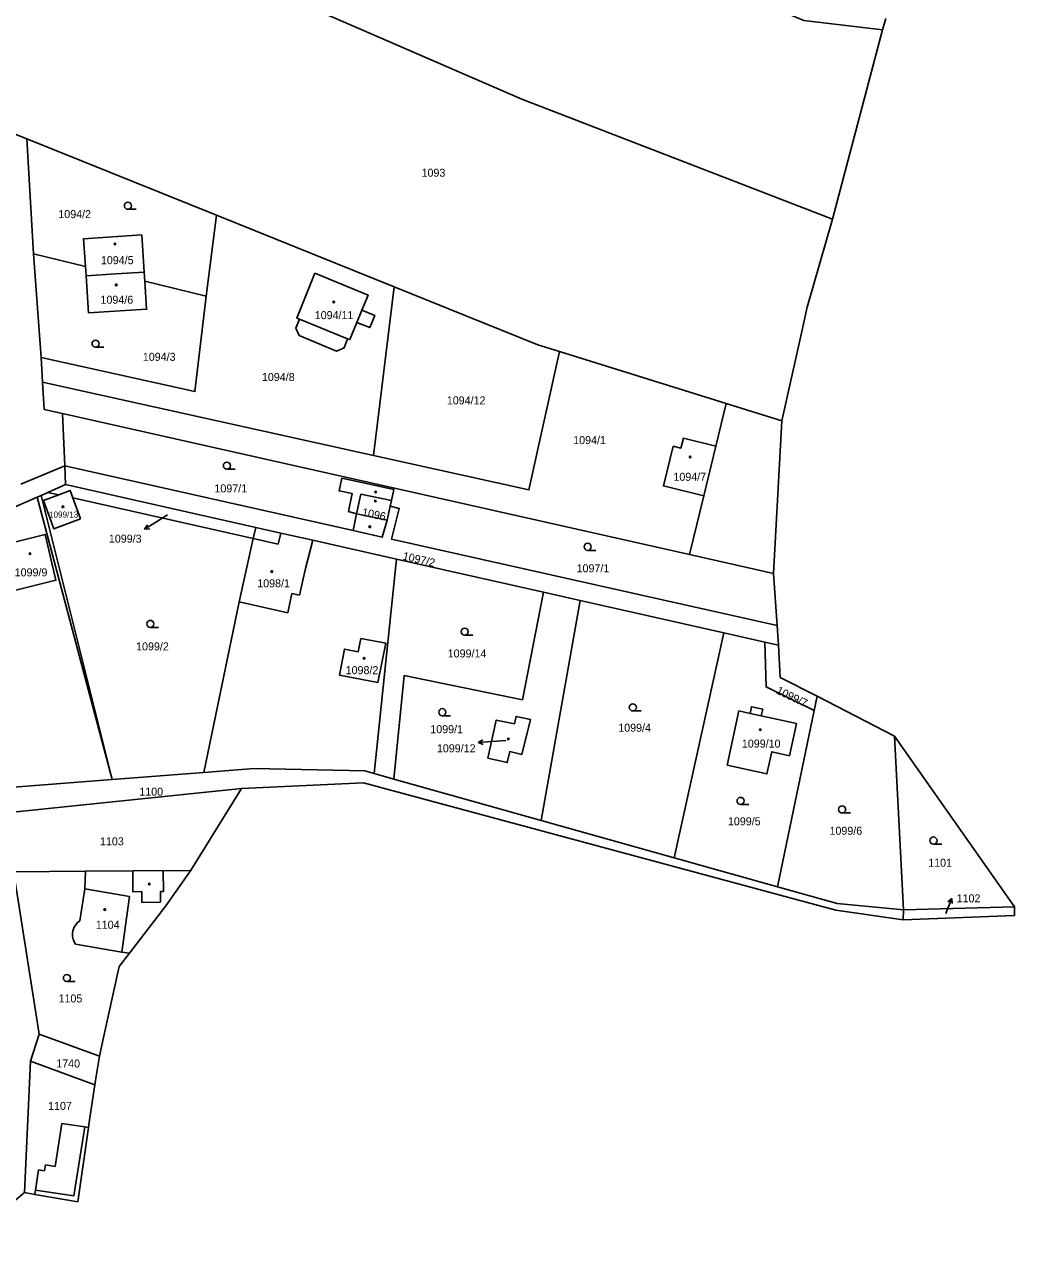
# Model space of a CAD drawing. Extents: x -724107 to -720612, y -1045267 to -1038441.
# Drawn here: x -721970.9 to -721760.5, y -1044478.1 to -1044219.7 of the extents above; entities that cross this region are included whole.
import ezdxf

# ---------------------------------------------------------------- set-up
doc = ezdxf.new("R2010")
doc.units = 0
for name, color, linetype in [('Hranice kat_území', 7, 'Continuous'), ('Hranice parcel', 7, 'Continuous'), ('Parcelní čísla', 7, 'Continuous'), ('Pop  PČ popisy', 7, 'Continuous'), ('Vnitřní kresba', 7, 'Continuous'), ('Značky budov', 7, 'Continuous'), ('Značky kultur', 7, 'Continuous')]:
    doc.layers.add(name, color=color, linetype=linetype)

msp = doc.modelspace()

# ---------------------------------------------------------------- linework, layer by layer
at = {"layer": 'Hranice kat_území'}
for p, q in [((-721788.61, -1044220.82), (-721787.91, -1044218.39)), ((-721799.2, -1044261.03), (-721788.61, -1044220.82)), ((-721809.96, -1044303.87), (-721805.88, -1044285.54)), ((-721811.72, -1044336.23), (-721809.96, -1044303.87)), ((-721810.96, -1044347.32), (-721811.72, -1044336.23)), ((-721810.68, -1044351.47), (-721810.96, -1044347.32)), ((-721786.01, -1044370.79), (-721802.48, -1044362.34)), ((-721760.55, -1044407.07), (-721786.01, -1044370.79)), ((-721935.62, -1044399.39), (-721924.74, -1044381.95)), ((-721940.82, -1044406.84), (-721935.62, -1044399.39)), ((-721948.56, -1044416.87), (-721940.82, -1044406.84)), ((-721798.52, -1044407.76), (-721784.21, -1044409.79)), ((-721784.21, -1044409.79), (-721760.51, -1044408.87)), ((-721760.55, -1044407.07), (-721760.51, -1044408.87)), ((-721954.95, -1044438.78), (-721954.21, -1044435.41)), ((-721955.57, -1044442.6), (-721954.95, -1044438.78)), ((-721955.93, -1044444.84), (-721955.57, -1044442.6))]:
    msp.add_line(p, q, dxfattribs=at)
for points in [[(-721805.88, -1044285.54), (-721804.58, -1044279.71), (-721799.2, -1044261.03)], [(-721802.48, -1044362.34), (-721810.3, -1044358.32), (-721810.68, -1044351.47)], [(-721924.74, -1044381.95), (-721898.87, -1044380.72), (-721798.52, -1044407.76)], [(-721954.21, -1044435.41), (-721950.76, -1044419.71), (-721948.56, -1044416.87)], [(-721957.14, -1044452.84), (-721956.99, -1044451.82), (-721955.93, -1044444.84)], [(-721959.54, -1044469.67), (-721957.29, -1044453.91), (-721957.14, -1044452.84)], [(-721970.87, -1044467.72), (-721972.74, -1044469.26), (-721979.36, -1044474.72), (-721983.52, -1044478.14)], [(-721959.54, -1044469.67), (-721968.69, -1044468.1), (-721970.87, -1044467.72)]]:
    msp.add_lwpolyline(points, dxfattribs=at)
at = {"layer": 'Hranice parcel'}
for p, q in [((-721975.92, -1044241.74), (-721970.35, -1044243.98)), ((-721970.35, -1044243.98), (-721930.09, -1044260.2)), ((-721970.35, -1044243.98), (-721968.98, -1044268.36)), ((-721932.24, -1044277.37), (-721930.09, -1044260.2)), ((-721930.09, -1044260.2), (-721892.33, -1044275.41)), ((-721968.98, -1044268.36), (-721957.91, -1044271.07)), ((-721968.98, -1044268.36), (-721967.36, -1044290.4)), ((-721957.78, -1044273.07), (-721957.91, -1044271.07)), ((-721945.46, -1044272.25), (-721945.34, -1044274.16)), ((-721945.34, -1044274.16), (-721932.24, -1044277.37)), ((-721896.72, -1044311.2), (-721892.33, -1044275.41)), ((-721857.19, -1044289.15), (-721821.77, -1044300.19)), ((-721967.03, -1044295.6), (-721967.36, -1044290.4)), ((-721896.72, -1044311.2), (-721967.03, -1044295.6)), ((-721821.77, -1044300.19), (-721809.96, -1044303.87)), ((-721962.77, -1044302.29), (-721829.61, -1044332.21)), ((-721962.32, -1044313.4), (-721962.77, -1044302.29)), ((-721971.64, -1044317.31), (-721962.32, -1044313.4)), ((-721962.32, -1044313.4), (-721901.08, -1044327.14)), ((-721962.32, -1044313.4), (-721962.16, -1044317.4)), ((-721965.9, -1044319.03), (-721962.16, -1044317.4)), ((-721962.16, -1044317.4), (-721921.75, -1044326.49)), ((-721967.33, -1044319.67), (-721965.9, -1044319.03)), ((-721952.21, -1044380), (-721967.33, -1044319.67)), ((-721966.83, -1044320.75), (-721963.56, -1044319.55)), ((-721963.56, -1044319.55), (-721965.9, -1044319.03)), ((-721960.58, -1044320.22), (-721958.97, -1044324.63)), ((-721922.27, -1044328.82), (-721960.58, -1044320.22)), ((-721922.27, -1044328.82), (-721921.75, -1044326.49)), ((-721896.57, -1044378.74), (-721891.86, -1044333.21)), ((-721891.86, -1044333.21), (-721860.58, -1044340.24)), ((-721829.61, -1044332.21), (-721811.72, -1044336.23)), ((-721860.58, -1044340.24), (-721852.85, -1044341.98)), ((-721861.08, -1044388.69), (-721852.85, -1044341.98)), ((-721852.85, -1044341.98), (-721822.32, -1044348.85)), ((-721832.85, -1044396.61), (-721822.32, -1044348.85)), ((-721822.32, -1044348.85), (-721813.61, -1044350.81)), ((-721813.61, -1044350.81), (-721810.68, -1044351.47)), ((-721802.48, -1044362.34), (-721803.11, -1044365.37)), ((-721810.87, -1044402.77), (-721803.11, -1044365.37)), ((-721784.16, -1044407.69), (-721786.01, -1044370.79)), ((-721978.83, -1044382.04), (-721952.21, -1044380)), ((-721932.77, -1044378.52), (-721952.21, -1044380)), ((-721892.41, -1044379.91), (-721896.57, -1044378.74)), ((-721892.41, -1044379.91), (-721861.08, -1044388.69)), ((-721977.33, -1044387.33), (-721924.74, -1044381.95)), ((-721861.08, -1044388.69), (-721832.85, -1044396.61)), ((-721832.85, -1044396.61), (-721810.87, -1044402.77)), ((-721973.2, -1044399.62), (-721957.88, -1044399.48)), ((-721784.21, -1044409.79), (-721784.16, -1044407.69)), ((-721784.16, -1044407.69), (-721760.55, -1044407.07)), ((-721967.74, -1044434.1), (-721969.56, -1044439.8)), ((-721967.74, -1044434.1), (-721954.95, -1044438.78)), ((-721969.56, -1044439.8), (-721970.87, -1044467.72)), ((-721955.93, -1044444.84), (-721969.56, -1044439.8))]:
    msp.add_line(p, q, dxfattribs=at)
for points in [[(-721961.47, -1044153.93), (-721895.13, -1044181.3), (-721805.29, -1044218.87), (-721788.61, -1044220.82)], [(-721968.11, -1044190.86), (-721865.19, -1044235.55), (-721799.2, -1044261.03)], [(-721957.91, -1044271.07), (-721958.3, -1044265.17), (-721945.97, -1044264.37), (-721945.46, -1044272.25)], [(-721957.78, -1044273.07), (-721951.48, -1044272.65), (-721945.46, -1044272.25)], [(-721945.34, -1044274.16), (-721944.95, -1044280.15), (-721957.26, -1044280.94), (-721957.78, -1044273.07)], [(-721899.21, -1044280.38), (-721896.46, -1044281.49), (-721897.5, -1044284.06), (-721900.26, -1044282.98), (-721901.73, -1044286.6), (-721902.25, -1044286.4), (-721902.96, -1044288.35), (-721904.56, -1044289.03), (-721912.53, -1044285.74), (-721913.26, -1044284.16), (-721912.45, -1044282.25), (-721912.99, -1044282.01), (-721909.16, -1044272.51), (-721897.89, -1044277.13), (-721899.21, -1044280.38)], [(-721892.33, -1044275.41), (-721861.83, -1044287.7), (-721857.19, -1044289.15)], [(-721967.36, -1044290.4), (-721934.68, -1044297.65), (-721932.24, -1044277.37)], [(-721857.19, -1044289.15), (-721863.7, -1044318.53), (-721896.72, -1044311.2)], [(-721967.03, -1044295.6), (-721966.66, -1044301.41), (-721962.77, -1044302.29)], [(-721829.61, -1044332.21), (-721826.56, -1044319.75), (-721835.14, -1044317.66), (-721833.06, -1044309.24), (-721831.4, -1044309.64), (-721830.89, -1044307.55), (-721823.99, -1044309.24), (-721821.77, -1044300.19)], [(-721893.21, -1044321.97), (-721892.91, -1044320.76), (-721892.38, -1044318.46), (-721903.45, -1044316.05), (-721904.03, -1044318.71), (-721901.24, -1044319.28), (-721902.03, -1044323.11), (-721900.31, -1044323.61), (-721901.08, -1044327.14)], [(-721967.33, -1044319.67), (-721968.19, -1044320.04), (-721998.33, -1044333.24)], [(-721958.97, -1044324.63), (-721964.66, -1044326.76), (-721966.83, -1044320.75)], [(-721963.56, -1044319.55), (-721961.15, -1044318.67), (-721960.58, -1044320.22)], [(-721901.08, -1044327.14), (-721894.86, -1044328.52), (-721893.85, -1044324.97), (-721893.21, -1044321.97)], [(-721893.21, -1044321.97), (-721891.27, -1044322.46), (-721892.91, -1044328.96), (-721810.96, -1044347.32)], [(-721972.97, -1044339.87), (-721976.27, -1044340.69), (-721978.48, -1044330.95), (-721975.23, -1044330.15), (-721966.5, -1044327.98), (-721964.21, -1044337.7), (-721972.97, -1044339.87)], [(-721932.77, -1044378.52), (-721925.29, -1044342.26), (-721922.27, -1044328.82)], [(-721921.75, -1044326.49), (-721916.44, -1044327.68), (-721909.6, -1044329.22), (-721891.86, -1044333.21)], [(-721860.58, -1044340.24), (-721865.09, -1044363.07), (-721890.21, -1044357.95), (-721892.41, -1044379.91)], [(-721895.79, -1044359.43), (-721903.92, -1044357.88), (-721902.9, -1044352.32), (-721899.95, -1044352.88), (-721899.41, -1044350.07), (-721894.13, -1044351.09), (-721895.79, -1044359.43)], [(-721803.11, -1044365.37), (-721813.32, -1044360.35), (-721813.61, -1044350.81)], [(-721821.61, -1044376.96), (-721819.1, -1044365.45), (-721816.73, -1044365.97), (-721816.42, -1044364.54), (-721814.03, -1044365.07), (-721814.35, -1044366.49), (-721806.87, -1044368.14), (-721808.38, -1044374.95), (-721812.11, -1044374.12), (-721813.15, -1044378.83), (-721821.61, -1044376.96)], [(-721872.42, -1044375.47), (-721870.64, -1044367.39), (-721866.8, -1044368.15), (-721866.42, -1044366.6), (-721863.39, -1044367.23), (-721865.21, -1044374.68), (-721867.77, -1044374.09), (-721868.3, -1044376.42), (-721872.42, -1044375.47)], [(-721896.57, -1044378.74), (-721898.55, -1044378.18), (-721922.09, -1044377.7), (-721932.77, -1044378.52)], [(-721973.2, -1044399.62), (-721972.16, -1044406.09), (-721967.74, -1044434.1)], [(-721957.88, -1044399.48), (-721958.04, -1044403.21), (-721959.14, -1044410.02)], [(-721957.88, -1044399.48), (-721947.83, -1044399.38), (-721941.4, -1044399.32), (-721935.62, -1044399.39)], [(-721810.87, -1044402.77), (-721798.21, -1044406.32), (-721784.16, -1044407.69)], [(-721959.14, -1044410.02), (-721959.6, -1044410.4), (-721959.99, -1044410.84), (-721960.31, -1044411.35), (-721960.53, -1044411.9), (-721960.6, -1044412.17), (-721960.68, -1044412.76), (-721960.66, -1044413.35), (-721960.55, -1044413.93), (-721960.33, -1044414.49), (-721960.03, -1044415)], [(-721960.03, -1044415), (-721950.16, -1044416.67), (-721948.56, -1044416.87)]]:
    msp.add_lwpolyline(points, dxfattribs=at)
at = {"layer": 'Pop  PČ popisy'}
for p, q in [((-721942.81, -1044325.29), (-721945.35, -1044326.88)), ((-721945.35, -1044326.88), (-721944.77, -1044325.93)), ((-721940.51, -1044323.83), (-721942.81, -1044325.29)), ((-721945.35, -1044326.88), (-721944.24, -1044326.77)), ((-721874.49, -1044372.17), (-721873.53, -1044371.6)), ((-721871.5, -1044371.96), (-721874.49, -1044372.17)), ((-721874.49, -1044372.17), (-721873.46, -1044372.6)), ((-721868.58, -1044371.75), (-721871.5, -1044371.96)), ((-721774.98, -1044408.02), (-721773.86, -1044405.24)), ((-721773.86, -1044405.24), (-721774.7, -1044405.98)), ((-721773.86, -1044405.24), (-721773.77, -1044406.35)), ((-721775.16, -1044408.45), (-721774.98, -1044408.02))]:
    msp.add_line(p, q, dxfattribs=at)
at = {"layer": 'Vnitřní kresba'}
for p, q in [((-721912.45, -1044282.25), (-721902.25, -1044286.4)), ((-721900.26, -1044282.98), (-721899.21, -1044280.38)), ((-721823.99, -1044309.24), (-721826.56, -1044319.75)), ((-721968.19, -1044320.04), (-721952.21, -1044380)), ((-721900.31, -1044323.61), (-721899.44, -1044319.4)), ((-721899.44, -1044319.4), (-721892.91, -1044320.76)), ((-721900.31, -1044323.61), (-721893.85, -1044324.97)), ((-721916.96, -1044330.01), (-721922.27, -1044328.82)), ((-721916.44, -1044327.68), (-721916.96, -1044330.01)), ((-721909.6, -1044329.22), (-721911.16, -1044335.21)), ((-721911.16, -1044335.21), (-721912.43, -1044340.85)), ((-721914.96, -1044344.59), (-721914.04, -1044340.49)), ((-721914.04, -1044340.49), (-721912.43, -1044340.85)), ((-721925.29, -1044342.26), (-721914.96, -1044344.59)), ((-721816.73, -1044365.97), (-721814.35, -1044366.49)), ((-721947.83, -1044399.38), (-721947.83, -1044403.83)), ((-721941.36, -1044403.77), (-721941.4, -1044399.32)), ((-721958.04, -1044403.21), (-721948.53, -1044404.88)), ((-721947.83, -1044403.83), (-721945.97, -1044403.81)), ((-721945.97, -1044403.81), (-721945.95, -1044406.1)), ((-721941.99, -1044403.78), (-721941.36, -1044403.77)), ((-721941.97, -1044406.07), (-721941.99, -1044403.78)), ((-721948.53, -1044404.88), (-721950.16, -1044416.67)), ((-721945.95, -1044406.1), (-721941.97, -1044406.07)), ((-721962.91, -1044453.07), (-721964.36, -1044462.15)), ((-721958.07, -1044453.79), (-721962.91, -1044453.07)), ((-721958.07, -1044453.79), (-721960.36, -1044468.39)), ((-721957.29, -1044453.91), (-721958.07, -1044453.79)), ((-721967.89, -1044462.92), (-721968.55, -1044467.19)), ((-721966.59, -1044463.13), (-721967.89, -1044462.92)), ((-721966.38, -1044461.83), (-721966.59, -1044463.13)), ((-721964.36, -1044462.15), (-721966.38, -1044461.83)), ((-721968.55, -1044467.19), (-721968.69, -1044468.1)), ((-721960.36, -1044468.39), (-721968.55, -1044467.19))]:
    msp.add_line(p, q, dxfattribs=at)
at = {"layer": 'Značky budov'}
for centre in [(-721951.64, -1044266.31), (-721951.38, -1044274.97), (-721905.16, -1044278.62), (-721829.45, -1044311.53), (-721896.32, -1044320.86), (-721896.25, -1044318.97), (-721962.71, -1044322.09), (-721897.52, -1044326.34), (-721969.71, -1044332.05), (-721918.33, -1044335.85), (-721898.71, -1044354.29), (-721814.56, -1044369.41), (-721868.09, -1044371.41), (-721944.35, -1044402.18), (-721953.81, -1044407.62)]:
    msp.add_circle(centre, 0.175, dxfattribs=at)
at = {"layer": 'Značky kultur'}
for p, q in [((-721948.9, -1044258.93), (-721947.15, -1044258.93)), ((-721955.77, -1044288.22), (-721954.02, -1044288.22)), ((-721927.87, -1044314.12), (-721926.12, -1044314.12)), ((-721851.22, -1044331.35), (-721849.47, -1044331.35)), ((-721944.15, -1044347.71), (-721942.4, -1044347.71)), ((-721877.35, -1044349.36), (-721875.6, -1044349.36)), ((-721882.1, -1044366.46), (-721880.35, -1044366.46)), ((-721841.63, -1044365.45), (-721839.88, -1044365.45)), ((-721818.74, -1044385.3), (-721816.99, -1044385.3)), ((-721797.17, -1044387.11), (-721795.42, -1044387.11)), ((-721777.76, -1044393.71), (-721776.01, -1044393.71)), ((-721961.86, -1044422.91), (-721960.11, -1044422.91))]:
    msp.add_line(p, q, dxfattribs=at)
for centre in [(-721948.9, -1044258.18), (-721955.77, -1044287.47), (-721927.87, -1044313.37), (-721851.22, -1044330.6), (-721944.15, -1044346.96), (-721877.35, -1044348.61), (-721882.1, -1044365.71), (-721841.63, -1044364.7), (-721818.74, -1044384.55), (-721797.17, -1044386.36), (-721777.76, -1044392.96), (-721961.86, -1044422.16)]:
    msp.add_circle(centre, 0.75, dxfattribs=at)

# ---------------------------------------------------------------- texts
at = {"layer": 'Parcelní čísla'}
for s, height, p in [('1093', 1.7, (-721886.52, -1044252.01)), ('1094/2', 1.7, (-721963.69, -1044260.8)), ('1094/5', 1.7, (-721954.64, -1044270.58)), ('1094/6', 1.7, (-721954.73, -1044278.98)), ('1094/11', 1.7, (-721909.21, -1044282.25)), ('1094/3', 1.7, (-721945.73, -1044291.1)), ('1094/8', 1.7, (-721920.43, -1044295.39)), ('1094/12', 1.7, (-721881.15, -1044300.35)), ('1094/1', 1.7, (-721854.3, -1044308.79)), ('1094/7', 1.7, (-721833.01, -1044316.58)), ('1097/1', 1.7, (-721930.52, -1044319.04)), ('1099/13', 1.288, (-721965.66, -1044324.39)), ('1099/3', 1.7, (-721952.95, -1044329.71)), ('1099/9', 1.7, (-721972.96, -1044336.87)), ('1097/1', 1.7, (-721853.58, -1044336.01)), ('1098/1', 1.7, (-721921.43, -1044339.2)), ('1099/2', 1.7, (-721947.16, -1044352.59)), ('1099/14', 1.7, (-721880.96, -1044354.09)), ('1098/2', 1.7, (-721902.65, -1044357.64)), ('1099/1', 1.7, (-721884.66, -1044370.17)), ('1099/4', 1.7, (-721844.73, -1044369.86)), ('1099/12', 1.7, (-721883.26, -1044374.24)), ('1099/10', 1.7, (-721818.47, -1044373.23)), ('1100', 1.7, (-721946.48, -1044383.44)), ('1099/5', 1.7, (-721821.43, -1044389.73)), ('1099/6', 1.7, (-721799.85, -1044391.74)), ('1103', 1.7, (-721954.83, -1044393.99)), ('1101', 1.7, (-721778.88, -1044398.53)), ('1102', 1.7, (-721772.84, -1044406.09)), ('1104', 1.7, (-721955.72, -1044411.69)), ('1105', 1.7, (-721963.64, -1044427.35)), ('1740', 1.7, (-721964.13, -1044441.15)), ('1107', 1.7, (-721965.86, -1044450.16))]:
    msp.add_text(s, height=height, dxfattribs=at).set_placement(p)
for s, rotation, p in [('1096', 348, (-721899.27, -1044323.99)), ('1097/2', 347, (-721890.64, -1044333.3)), ('1099/7', 334, (-721811.31, -1044361.66))]:
    msp.add_text(s, height=1.7, rotation=rotation, dxfattribs=at).set_placement(p)

doc.saveas('drawing.dxf')
